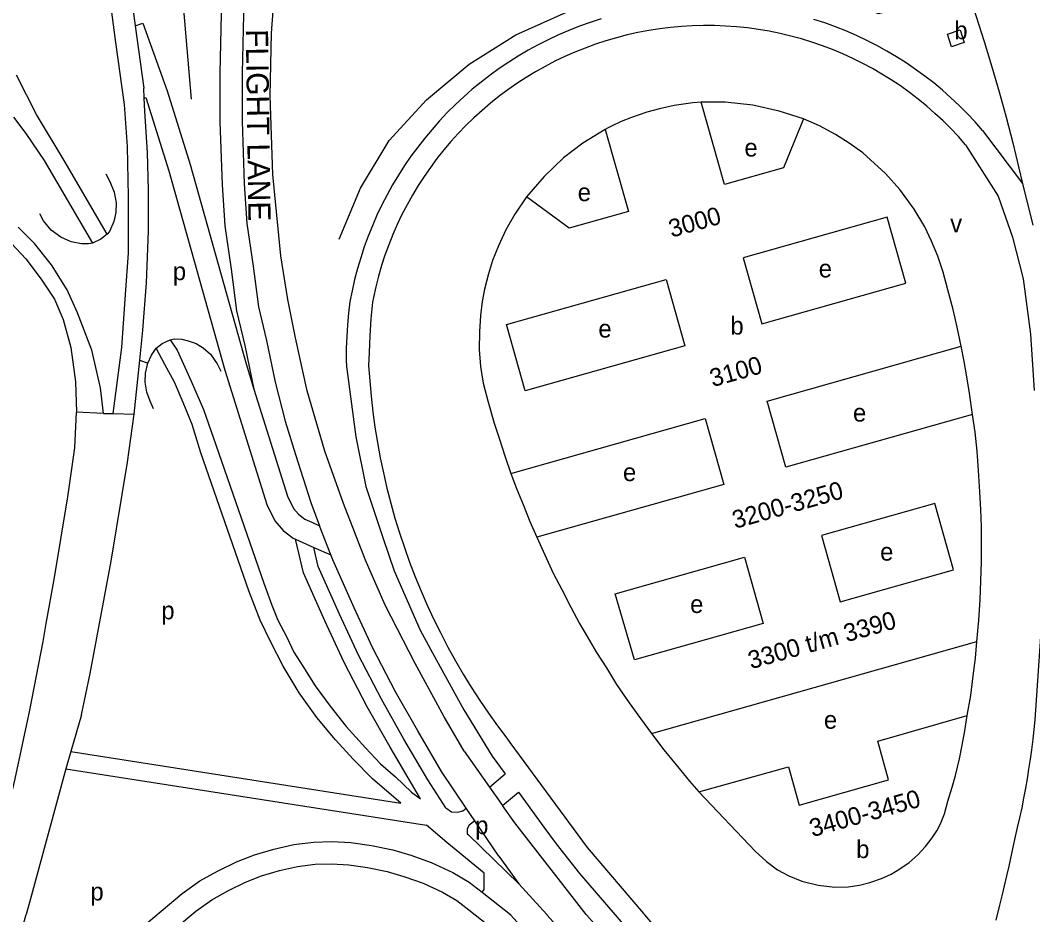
# Model space of a CAD drawing. Extents: x 154765 to 156627, y 383996 to 386132.
# Drawn here: x 155994.8 to 156222.1, y 384500 to 384700.7 of the extents above; entities that cross this region are included whole.
import ezdxf

# ---------------------------------------------------------------- set-up
doc = ezdxf.new("R2010")
doc.units = 0
for name, color, linetype in [('BLT_Basislijn', 7, 'Continuous'), ('BLT_Bebouwing', 7, 'Continuous'), ('BLT_Centroide', 7, 'Continuous'), ('BLT_Huisnummer_reeks', 7, 'Continuous'), ('BLT_Straatnaam', 7, 'Continuous'), ('BLT_Vlakafsluiter', 7, 'Continuous')]:
    doc.layers.add(name, color=color, linetype=linetype)

msp = doc.modelspace()

# ---------------------------------------------------------------- linework, layer by layer
at = {"layer": 'BLT_Basislijn'}
for p, q in [((156051.2, 384697.77), (156052.39, 384714.22)), ((156020.01, 384703.9), (156020.62, 384699.44)), ((156016.28, 384695.72), (156015.36, 384702.5)), ((156020.62, 384699.44), (156022.52, 384685.48)), ((156050.9, 384683.71), (156051.2, 384697.77)), ((156018.21, 384681.82), (156016.28, 384695.72)), ((155998.44, 384679.58), (155993.92, 384688.4)), ((156022.61, 384683.21), (156022.52, 384685.48)), ((156022.73, 384680.31), (156022.61, 384683.21)), ((156051.5, 384666.07), (156050.9, 384683.71)), ((156018.86, 384672.34), (156018.21, 384681.82)), ((155993.28, 384678.94), (155996.07, 384675.28)), ((156004.89, 384668.83), (155998.44, 384679.58)), ((156023.38, 384671.05), (156022.73, 384680.31)), ((156210.86, 384675.98), (156219.83, 384664.1)), ((155996.07, 384675.28), (156000.16, 384669.26)), ((156019.07, 384661.13), (156018.86, 384672.34)), ((156207.06, 384672.73), (156214.35, 384661.21)), ((156000.16, 384669.26), (156011.01, 384650.71)), ((156023.59, 384662.64), (156023.38, 384671.05)), ((156012.51, 384655.75), (156004.89, 384668.83)), ((156053.29, 384647.82), (156051.5, 384666.07)), ((156023.59, 384653.38), (156023.59, 384662.64)), ((156219.83, 384664.1), (156222.15, 384654.75)), ((156019.07, 384648.42), (156019.07, 384661.13)), ((156214.35, 384661.21), (156217.58, 384652.06)), ((156014.3, 384652.72), (156012.51, 384655.75)), ((155997.96, 384650.58), (155994.3, 384654.24)), ((156023.16, 384641.74), (156023.59, 384653.38)), ((156217.58, 384652.06), (156220, 384642.64)), ((155992.8, 384650.58), (155996.03, 384647.13)), ((156001.84, 384645.84), (155997.96, 384650.58)), ((155996.03, 384647.13), (155999.47, 384642.6)), ((156018.42, 384639.16), (156019.07, 384648.42)), ((156054.84, 384638.01), (156053.29, 384647.82)), ((156005.29, 384640.23), (156001.84, 384645.84)), ((155999.47, 384642.6), (156002.49, 384638.08)), ((156022.3, 384631.18), (156023.16, 384641.74)), ((156220, 384642.64), (156221.62, 384630.26)), ((156007.66, 384635.06), (156005.29, 384640.23)), ((156002.49, 384638.08), (156004.43, 384633.55)), ((156017.56, 384627.3), (156018.42, 384639.16)), ((156056.62, 384629.46), (156054.84, 384638.01)), ((156010.89, 384626.66), (156007.66, 384635.06)), ((156004.43, 384633.55), (156006.15, 384627.3)), ((156021.64, 384624.4), (156022.3, 384631.18)), ((156028.45, 384628.98), (156030, 384626.66)), ((156059.21, 384617.53), (156056.62, 384629.46)), ((156221.62, 384630.26), (156222.42, 384617.61)), ((156006.15, 384627.3), (156007.23, 384619.55)), ((156012.83, 384618.25), (156010.89, 384626.66)), ((156015.62, 384612.44), (156017.56, 384627.3)), ((156027.22, 384623.48), (156025.29, 384627.08)), ((156030, 384626.66), (156033.18, 384619.7)), ((156021.22, 384620.19), (156021.64, 384624.4)), ((156029.41, 384619.5), (156027.22, 384623.48)), ((156068.02, 384622.98), (156070.15, 384607.25)), ((156007.23, 384619.55), (156007.44, 384612.74)), ((156020.36, 384612.31), (156021.22, 384620.19)), ((156031.39, 384614.93), (156029.41, 384619.5)), ((156033.18, 384619.7), (156035.96, 384613.34)), ((156013.47, 384612.44), (156012.83, 384618.25)), ((156063.18, 384604.02), (156059.21, 384617.53)), ((156033.38, 384609.96), (156031.39, 384614.93)), ((156007.01, 384604.76), (156007.44, 384612.74)), ((156013.47, 384612.44), (156015.62, 384612.44)), ((156018.86, 384601.53), (156020.36, 384612.31)), ((156035.96, 384613.34), (156038.74, 384605.43)), ((156035.37, 384603.64), (156033.38, 384609.96)), ((156038.74, 384605.43), (156049.47, 384574.42)), ((156070.15, 384607.25), (156072.38, 384596.11)), ((156005.5, 384593.78), (156007.01, 384604.76)), ((156046.09, 384572.63), (156035.37, 384603.64)), ((156067.35, 384592.29), (156063.18, 384604.02)), ((156015.19, 384579.34), (156018.86, 384601.53)), ((156072.38, 384596.11), (156076.27, 384584.41)), ((156002.49, 384575.68), (156005.5, 384593.78)), ((156072.32, 384579.57), (156067.35, 384592.29)), ((156064.52, 384580.76), (156062.01, 384587.28)), ((156056.6, 384584.23), (156060.7, 384582.4)), ((156076.27, 384584.41), (156078.78, 384577.17)), ((156060.7, 384582.4), (156064.52, 384580.76)), ((156064.97, 384579.59), (156064.52, 384580.76)), ((156010.46, 384554.13), (156015.19, 384579.34)), ((156069.73, 384568.86), (156064.97, 384579.59)), ((156076.69, 384569.43), (156072.32, 384579.57)), ((156078.78, 384577.17), (156084.62, 384563.8)), ((156000.6, 384565.31), (156002.49, 384575.68)), ((156049.47, 384574.42), (156051.26, 384569.45)), ((156048.68, 384566.08), (156046.09, 384572.63)), ((156051.26, 384569.45), (156052.65, 384566.08)), ((156083.44, 384556.32), (156076.69, 384569.43)), ((156073.91, 384559.91), (156069.73, 384568.86)), ((156051.06, 384561.11), (156048.68, 384566.08)), ((156052.65, 384566.08), (156054.64, 384562.3)), ((156054.64, 384562.3), (156056.23, 384558.92)), ((156084.62, 384563.8), (156088.24, 384557.12)), ((156053.84, 384555.74), (156051.06, 384561.11)), ((156079.07, 384549.98), (156073.91, 384559.91)), ((156056.23, 384558.92), (156058.21, 384555.74)), ((156057.42, 384549.78), (156053.84, 384555.74)), ((156058.21, 384555.74), (156060.99, 384551.37)), ((156090, 384544.39), (156083.44, 384556.32)), ((156088.24, 384557.12), (156094.37, 384545.98)), ((156008.52, 384544.86), (156010.46, 384554.13)), ((156060.99, 384551.37), (156064.37, 384546.8)), ((156061.39, 384544.21), (156057.42, 384549.78)), ((156084.04, 384541.23), (156079.07, 384549.98)), ((156064.37, 384546.8), (156067.95, 384542.23)), ((156008.52, 384544.86), (156006.16, 384536.6)), ((156065.56, 384539.24), (156061.39, 384544.21)), ((156094.47, 384536.72), (156090, 384544.39)), ((156094.37, 384545.98), (156100.77, 384535.59)), ((156067.95, 384542.23), (156072.32, 384537.45)), ((156089.4, 384532.09), (156084.04, 384541.23)), ((156069.54, 384534.87), (156065.56, 384539.24)), ((156072.32, 384537.45), (156075.69, 384533.88)), ((156084.63, 384525.99), (156077.83, 384537.59)), ((156006.16, 384536.6), (156005, 384532.73)), ((156006.16, 384536.6), (156080.25, 384525.03)), ((156073.91, 384530.5), (156069.54, 384534.87)), ((156094.47, 384536.72), (156100.18, 384528.61)), ((156100.77, 384535.59), (156103.7, 384531.57)), ((156005, 384532.73), (156086.04, 384520.08)), ((156075.69, 384533.88), (156079.07, 384530.9)), ((156080.25, 384525.03), (156073.91, 384530.5)), ((156079.07, 384530.9), (156082.65, 384527.52)), ((156094.94, 384523.93), (156089.4, 384532.09)), ((156100.18, 384528.61), (156103.7, 384531.57)), ((156100.18, 384528.61), (156103.06, 384524.5)), ((156082.65, 384527.52), (156084.63, 384525.99)), ((156103.06, 384524.5), (156106.65, 384527.51)), ((156096.88, 384521.07), (156094.94, 384523.93)), ((156105.83, 384520.57), (156103.06, 384524.5)), ((156090.59, 384516.19), (156086.04, 384520.08)), ((156102.25, 384513.11), (156096.88, 384521.07)), ((156121.89, 384500), (156105.83, 384520.57)), ((156098.94, 384509.3), (156090.59, 384516.19)), ((156098.94, 384505.65), (156098.94, 384509.3)), ((156098.54, 384505.06), (156098.94, 384505.65)), ((156095.52, 384501.07), (156101.2, 384496.63)), ((156121.91, 384499.98), (156121.89, 384500)), ((156121.91, 384499.98), (156131.18, 384489.58)), ((156128.33, 384499.98), (156130.93, 384496.97)), ((156134.71, 384500.24), (156134.92, 384500)), ((156134.92, 384500), (156134.93, 384499.98)), ((156134.93, 384499.98), (156169.64, 384459.92))]:
    msp.add_line(p, q, dxfattribs=at)
for points in [[(156066.37, 384651.6), (156071.21, 384663.04), (156077.65, 384673.68), (156086.03, 384682.85), (156095.55, 384690.85), (156106.1, 384697.42), (156117.43, 384702.54), (156129.38, 384705.93), (156141.61, 384708.16), (156154.02, 384708.97), (156166.44, 384708.53), (156178.54, 384705.69), (156187.51, 384702.21), (156199.99, 384705.41), (156195.34, 384718.5), (156187.31, 384738.53), (156176.24, 384761.35), (156165.68, 384783.11), (156154.18, 384802.19), (156126.58, 384844.77)], [(156184.81, 384761.44), (156187.42, 384756.16), (156189.95, 384750.83), (156192.41, 384745.48), (156194.8, 384740.09), (156197.12, 384734.67), (156199.36, 384729.22), (156201.52, 384723.73), (156203.62, 384718.22), (156205.63, 384712.68), (156207.58, 384707.12), (156209.44, 384701.53), (156211.23, 384695.91), (156212.95, 384690.27), (156214.58, 384684.61), (156216.14, 384678.93), (156217.62, 384673.22), (156219.03, 384667.5), (156219.83, 384664.1)], [(156030.93, 384757.84), (156028.96, 384733.75), (156030.39, 384715.44), (156033.16, 384683.02)], [(156046.25, 384756.35), (156044.49, 384748.03), (156042.98, 384738.5), (156041.58, 384725.51), (156040.53, 384715.49), (156039.92, 384702.13), (156039.62, 384688.85), (156039.62, 384677.94), (156040.11, 384663.77), (156040.72, 384654.55), (156042.13, 384644.85), (156043.35, 384635.49), (156045.19, 384627.74), (156047.27, 384617.95)], [(156051.26, 384755.87), (156049.4, 384747.12), (156047.94, 384737.84), (156046.55, 384724.99), (156045.52, 384715.12), (156044.92, 384701.96), (156044.62, 384688.8), (156044.62, 384678.03), (156045.1, 384664.02), (156045.7, 384655.08), (156047.09, 384645.54), (156048.28, 384636.39), (156050.07, 384628.84), (156052.05, 384619.5), (156054.24, 384610.75), (156056.62, 384603.24), (156060, 384592.51), (156062.01, 384587.28)], [(156125.21, 384700.98), (156122.78, 384700.2), (156120.38, 384699.34), (156118, 384698.41), (156115.65, 384697.41), (156113.34, 384696.33), (156111.06, 384695.17), (156108.82, 384693.95), (156106.62, 384692.66), (156104.46, 384691.3), (156102.35, 384689.87), (156100.28, 384688.38), (156098.26, 384686.82), (156096.28, 384685.2), (156094.36, 384683.52), (156092.5, 384681.78), (156090.68, 384679.98), (156088.93, 384678.13), (156087.24, 384676.22), (156085.6, 384674.26), (156084.03, 384672.25), (156082.52, 384670.19), (156081.08, 384668.09), (156079.7, 384665.94), (156078.39, 384663.74), (156077.15, 384661.51), (156075.98, 384659.25), (156074.89, 384656.94), (156073.86, 384654.6), (156072.91, 384652.24), (156072.03, 384649.84), (156071.23, 384647.41), (156070.51, 384644.97), (156069.86, 384642.5), (156069.29, 384640.01), (156068.82, 384637.58)], [(156210.86, 384675.98), (156209.18, 384677.89), (156207.43, 384679.75), (156205.62, 384681.55), (156203.77, 384683.3), (156201.85, 384684.99), (156199.89, 384686.62), (156197.87, 384688.18), (156195.8, 384689.68), (156193.7, 384691.12), (156191.54, 384692.49), (156189.35, 384693.79), (156187.11, 384695.02), (156184.84, 384696.18), (156182.53, 384697.27), (156180.19, 384698.29), (156177.82, 384699.23), (156175.42, 384700.1), (156172.99, 384700.89)], [(156020.62, 384699.44), (156022.3, 384700.03), (156027.8, 384684.85), (156032.91, 384668.32), (156045.49, 384623.63), (156047.27, 384617.95)], [(156207.06, 384672.73), (156205.43, 384674.58), (156203.73, 384676.38), (156201.98, 384678.13), (156200.17, 384679.81), (156198.31, 384681.44), (156196.4, 384683.01), (156194.43, 384684.51), (156192.42, 384685.95), (156190.37, 384687.32), (156188.27, 384688.63), (156186.13, 384689.87), (156183.95, 384691.03), (156181.73, 384692.13), (156179.48, 384693.16), (156177.2, 384694.11), (156174.89, 384694.98), (156172.55, 384695.79), (156170.18, 384696.51), (156167.8, 384697.16), (156165.39, 384697.73), (156162.97, 384698.22), (156160.53, 384698.64), (156158.08, 384698.97), (156155.62, 384699.23), (156153.15, 384699.4), (156150.68, 384699.5), (156148.21, 384699.52), (156145.74, 384699.45), (156143.27, 384699.31), (156140.81, 384699.09), (156138.36, 384698.78), (156135.91, 384698.4), (156133.48, 384697.94), (156131.07, 384697.4), (156128.68, 384696.78), (156126.3, 384696.09), (156123.95, 384695.32), (156121.63, 384694.47), (156119.34, 384693.55), (156117.07, 384692.56), (156114.84, 384691.49), (156112.65, 384690.35), (156110.49, 384689.14), (156108.37, 384687.86), (156106.3, 384686.52), (156104.27, 384685.1), (156102.29, 384683.63), (156100.35, 384682.09), (156098.47, 384680.48), (156096.64, 384678.82), (156094.87, 384677.1), (156093.15, 384675.32), (156091.49, 384673.49), (156089.89, 384671.6), (156088.35, 384669.67), (156086.87, 384667.68), (156085.46, 384665.65), (156084.12, 384663.58), (156082.84, 384661.46), (156081.64, 384659.3), (156080.5, 384657.1), (156079.44, 384654.87), (156078.45, 384652.61), (156077.53, 384650.31), (156076.68, 384647.99), (156075.92, 384645.64), (156075.23, 384643.26), (156074.61, 384640.87), (156074.08, 384638.45), (156073.88, 384637.46)], [(156022.61, 384683.21), (156023.02, 384683.37), (156028.12, 384666.9), (156040.7, 384622.21), (156050.14, 384592.04), (156051.97, 384588.36), (156053.82, 384586.22), (156056.06, 384584.49), (156056.6, 384584.23)], [(156170.67, 384678.6), (156165.21, 384680.33), (156159.3, 384681.64), (156153.1, 384682.29), (156147.7, 384682.28)], [(156126.12, 384676.22), (156121.13, 384673.15), (156116.78, 384669.85), (156112.39, 384665.64), (156108.47, 384661.08)], [(156013.97, 384666.26), (156014.93, 384664.49), (156015.91, 384662.12), (156016.32, 384659.71), (156016.27, 384657.57), (156015.81, 384655.53), (156014.81, 384653.32), (156014.3, 384652.72)], [(156011.01, 384650.71), (156010.12, 384650.51), (156008.54, 384650.54), (156006.19, 384651), (156003.88, 384651.99), (156001.75, 384653.61), (156000, 384655.68), (155999.16, 384657.29)], [(156014.3, 384652.72), (156012.86, 384651.54), (156011.01, 384650.71)], [(156068.82, 384637.58), (156068.49, 384634.97), (156068.25, 384632.35), (156068.08, 384629.72), (156067.99, 384627.09), (156067.99, 384624.46), (156068.02, 384622.98)], [(156073.88, 384637.46), (156073.54, 384633.69), (156073.28, 384629.92), (156073.1, 384626.14), (156073.01, 384623.26)], [(156025.29, 384627.08), (156026.66, 384628.19), (156028.45, 384628.98)], [(156028.45, 384628.98), (156029.41, 384629.19), (156031.05, 384629.1), (156032.47, 384628.79), (156034.27, 384628.13), (156035.85, 384627.21), (156037.48, 384625.76), (156039.01, 384623.63), (156039.84, 384621.96)], [(156023.42, 384623.78), (156024.23, 384625.57), (156025.29, 384627.08)], [(156208.62, 384612.25), (156207.96, 384617.03), (156207.36, 384620.66), (156206.73, 384624.09), (156206.05, 384627.53)], [(156024.73, 384613.5), (156023.96, 384615.19), (156023.21, 384617.25), (156022.84, 384619.52), (156022.92, 384621.54), (156023.42, 384623.78)], [(156073.01, 384623.26), (156073.25, 384619.79), (156073.57, 384616.32), (156073.96, 384612.86), (156074.44, 384609.4), (156074.99, 384605.96), (156075.62, 384602.54), (156076.33, 384599.12), (156077.12, 384595.73), (156077.99, 384592.36), (156078.93, 384589), (156079.95, 384585.67), (156081.05, 384582.36), (156082.22, 384579.08), (156083.47, 384575.83), (156084.79, 384572.61), (156086.19, 384569.41), (156087.66, 384566.26), (156089.2, 384563.13), (156090.81, 384560.04), (156092.49, 384556.99), (156094.25, 384553.98), (156096.07, 384551.01), (156097.96, 384548.08), (156099.91, 384545.2), (156101.93, 384542.36), (156104.02, 384539.57), (156104.73, 384538.64)], [(156047.27, 384617.95), (156054.79, 384593.91), (156056.16, 384591.15), (156057.27, 384589.87), (156058.69, 384588.78), (156060.23, 384588.05), (156062.01, 384587.28)], [(156104.97, 384599.02), (156106.25, 384595.64), (156107.7, 384592.04), (156109.22, 384588.24), (156110.78, 384584.68)], [(156067.52, 384556.59), (156063.15, 384565.93), (156058.39, 384576.67), (156056.6, 384584.23)], [(156070.71, 384558.25), (156066.44, 384567.4), (156061.68, 384578.13), (156060.7, 384582.4)], [(156224.84, 384576.69), (156222.6, 384543.73), (156222.39, 384541.55), (156222.13, 384539.38), (156221.83, 384536.99), (156221.55, 384534.88), (156221.2, 384532.61), (156220.9, 384530.49), (156220.5, 384528.38), (156220.08, 384526.14), (156219.64, 384523.94), (156219.16, 384521.76), (156218.63, 384519.59), (156218.2, 384517.5), (156217.67, 384515.17), (156216.75, 384510.87), (156216.23, 384508.74), (156215.68, 384506.44), (156215.19, 384504.21), (156214.7, 384502.11), (156213.86, 384498.76)], [(155991.54, 384521.43), (155991.88, 384522.85), (155993.64, 384530.51), (155995.32, 384538.19), (155996.93, 384545.89), (155998.45, 384553.6), (155999.9, 384561.32), (156000.6, 384565.31)], [(156207.43, 384544.71), (156208.22, 384549.19), (156208.73, 384553.58), (156209.27, 384557.57), (156209.61, 384561.3)], [(156080.93, 384539.41), (156075.88, 384548.32), (156070.71, 384558.25)], [(156077.83, 384537.59), (156072.68, 384546.66), (156067.52, 384556.59)], [(156090.35, 384523.96), (156086.3, 384530.27), (156080.93, 384539.41)], [(156136.55, 384540.65), (156139.29, 384537.02), (156142.08, 384533.61), (156145.09, 384529.98), (156147.13, 384527.59)], [(156104.73, 384538.64), (156122.07, 384515.08), (156134.71, 384500.24)], [(156005, 384532.73), (155997.06, 384503.55), (155996.08, 384500)], [(156106.65, 384527.51), (156112.37, 384519.65)], [(156090.35, 384523.96), (156091.59, 384523.09), (156093.02, 384522.97), (156094.14, 384523.28), (156094.94, 384523.93)], [(156096.88, 384521.07), (156095.59, 384520.06), (156095.1, 384519.24), (156095.1, 384518.14), (156095.4, 384517.92), (156106.77, 384506.95)], [(156112.37, 384519.65), (156115.12, 384515.87), (156120.34, 384509.23), (156128.31, 384500)], [(156020.72, 384495.99), (156026.44, 384500.79), (156031.14, 384504.76), (156035.1, 384507.56), (156039.06, 384509.77), (156043.34, 384511.88), (156047.38, 384513.42), (156051.69, 384514.72), (156056.18, 384515.74), (156060.64, 384516.3), (156064.77, 384516.4), (156069.05, 384516.19), (156073.65, 384515.53), (156078.42, 384514.54), (156082.45, 384513.32), (156087.08, 384511.7), (156091.92, 384509.49), (156095.6, 384507.28), (156098.54, 384505.06)], [(156102.25, 384513.11), (156106.77, 384506.95)], [(156029.66, 384496.97), (156034.2, 384500.8), (156037.77, 384503.33), (156041.39, 384505.34), (156045.34, 384507.29), (156048.99, 384508.69), (156052.97, 384509.88), (156057.05, 384510.81), (156061.01, 384511.3), (156064.71, 384511.4), (156068.57, 384511.21), (156072.78, 384510.6), (156077.18, 384509.69), (156080.9, 384508.56), (156085.22, 384507.06), (156089.59, 384505.06), (156092.8, 384503.14), (156095.52, 384501.07)], [(156106.77, 384506.95), (156113.04, 384500)], [(156098.54, 384505.06), (156104.88, 384500)], [(155996.07, 384499.98), (155993.94, 384492.5), (155991.73, 384485.04), (155989.75, 384478.59)], [(155996.08, 384500), (155996.07, 384499.98)], [(156104.88, 384500), (156104.9, 384499.98)], [(156104.9, 384499.98), (156117.52, 384486.02)], [(156113.04, 384500), (156113.06, 384499.98)], [(156113.06, 384499.98), (156130.41, 384480.75)], [(156128.31, 384500), (156128.33, 384499.98)]]:
    msp.add_lwpolyline(points, dxfattribs=at)
at = {"layer": 'BLT_Bebouwing'}
msp.add_line((156136.55, 384540.65), (156209.61, 384561.3), dxfattribs=at)
for points in [[(156202.97, 384697.6), (156205.8, 384698.53), (156206.73, 384695.69), (156203.9, 384694.76)], [(156193.65, 384641.68), (156189.46, 384656.54), (156157.1, 384647.42), (156161.3, 384632.55)], [(156103.95, 384632.44), (156139.81, 384642.54), (156143.99, 384627.65), (156108.15, 384617.54)], [(156200.11, 384592.25), (156174.69, 384585.09), (156178.91, 384570.19), (156204.32, 384577.38)], [(156128.38, 384572.02), (156157.37, 384580.18), (156161.57, 384565.31), (156132.69, 384557.19)]]:
    msp.add_lwpolyline(points, close=True, dxfattribs=at)
for points in [[(156147.7, 384682.28), (156145.82, 384682.14), (156141.58, 384681.54), (156138.3, 384680.84), (156135.5, 384680.08), (156132.02, 384678.9), (156129.74, 384678.01), (156127.54, 384676.9), (156126.78, 384676.59), (156126.12, 384676.22)], [(156170.67, 384678.6), (156166.18, 384667.61), (156152.89, 384663.85), (156147.7, 384682.28)], [(156206.05, 384627.53), (156205.14, 384631.82), (156204.23, 384635.77), (156203.07, 384640.19), (156201.99, 384644.16), (156200.83, 384647.75), (156199.42, 384651.16), (156197.89, 384654.31), (156195.52, 384658.29), (156192.29, 384662.73), (156189.1, 384666.28), (156185.72, 384669.37), (156183.97, 384670.93), (156180.9, 384673.14), (156177.85, 384675.06), (156174.26, 384677.02), (156170.67, 384678.6)], [(156126.12, 384676.22), (156131.35, 384657.79), (156118.04, 384654.05), (156108.47, 384661.08)], [(156108.47, 384661.08), (156105.82, 384657.22), (156103.79, 384653.66), (156102.16, 384650.09), (156100.85, 384646.75), (156099.89, 384643.76), (156099.06, 384640.39), (156098.51, 384637.6), (156098.11, 384634.48), (156097.9, 384630.78), (156097.82, 384626.79), (156098.15, 384623.01), (156098.73, 384619.24), (156099.76, 384615.33), (156101.23, 384610.32), (156102.39, 384606.66), (156103.59, 384602.99), (156104.97, 384599.02)], [(156208.62, 384612.25), (156166.65, 384600.43), (156162.47, 384615.25), (156206.05, 384627.53)], [(156209.61, 384561.3), (156210.01, 384566.05), (156210.3, 384570.66), (156210.48, 384574.9), (156210.59, 384579.14), (156210.64, 384583.37), (156210.61, 384587.03), (156210.46, 384590.95), (156210.26, 384594.9), (156209.93, 384599.68), (156209.64, 384604.03), (156209.17, 384608.27), (156208.62, 384612.25)], [(156104.97, 384599.02), (156148.6, 384611.31), (156152.77, 384596.51), (156110.78, 384584.68)], [(156110.78, 384584.68), (156112.59, 384580.75), (156114.48, 384576.65), (156116.4, 384572.99), (156118.42, 384568.99), (156120.39, 384565.36), (156122.06, 384562.44), (156124.2, 384558.85), (156126.4, 384555.38), (156128.7, 384551.64), (156131.53, 384547.54), (156134.07, 384544.02), (156136.55, 384540.65)], [(156147.13, 384527.59), (156167.25, 384533.2), (156169.7, 384524.59), (156189.75, 384530.27), (156187.32, 384538.91), (156207.43, 384544.71)], [(156147.13, 384527.59), (156159.8, 384514.21), (156162.34, 384511.89), (156164.81, 384510.08), (156167.35, 384508.7), (156170.25, 384507.54), (156173.91, 384506.6), (156177.66, 384506.2), (156180.7, 384506.23), (156183.2, 384506.63), (156185.56, 384507.25), (156188.17, 384508.08), (156190.35, 384509.1), (156192.27, 384510.26), (156194.37, 384511.67), (156196.35, 384513.41), (156198.04, 384515.26), (156199.52, 384517.26), (156200.57, 384518.82), (156201.44, 384520.35), (156202.28, 384522.66), (156203.08, 384525.46), (156204.06, 384528.61), (156204.78, 384531.22), (156205.65, 384534.96), (156206.31, 384538.04), (156206.89, 384541.27), (156207.43, 384544.71)]]:
    msp.add_lwpolyline(points, dxfattribs=at)
at = {"layer": 'BLT_Vlakafsluiter'}
for p, q in [((156021.64, 384624.4), (156023.42, 384623.78)), ((156013.47, 384612.44), (156007.44, 384612.74)), ((156015.62, 384612.44), (156020.36, 384612.31))]:
    msp.add_line(p, q, dxfattribs=at)

# ---------------------------------------------------------------- texts
at = {"layer": 'BLT_Centroide'}
for s, p in [('b', (156204.53, 384696.45)), ('e', (156157.39, 384670.12)), ('e', (156119.96, 384660.11)), ('v', (156203.59, 384653.08)), ('p', (156029.05, 384642.37)), ('e', (156174.08, 384642.99)), ('e', (156124.6, 384629.5)), ('b', (156154.25, 384630.16)), ('e', (156181.77, 384610.64)), ('e', (156130.12, 384597.29)), ('e', (156187.86, 384579.44)), ('p', (156026.47, 384566.27)), ('e', (156145.2, 384567.69)), ('e', (156175.24, 384541.72)), ('p', (156096.93, 384518.05)), ('b', (156182.49, 384512.69)), ('p', (156010.55, 384503.19))]:
    msp.add_text(s, height=4, dxfattribs=at).set_placement(p)
at = {"layer": 'BLT_Huisnummer_reeks'}
for s, p in [('3000', (156141.03, 384651.89)), ('3100', (156150.26, 384618.36)), ('3200-3250', (156155.3, 384586.56)), ('3300 t/m 3390', (156158.87, 384555.06)), ('3400-3450', (156172.64, 384517.37))]:
    msp.add_text(s, height=4, rotation=15.7583, dxfattribs=at).set_placement(p)
at = {"layer": 'BLT_Straatnaam'}
msp.add_text('FLIGHT LANE', height=5, rotation=270.7852, dxfattribs=at).set_placement((156045.43, 384698.66))

doc.saveas('drawing.dxf')
